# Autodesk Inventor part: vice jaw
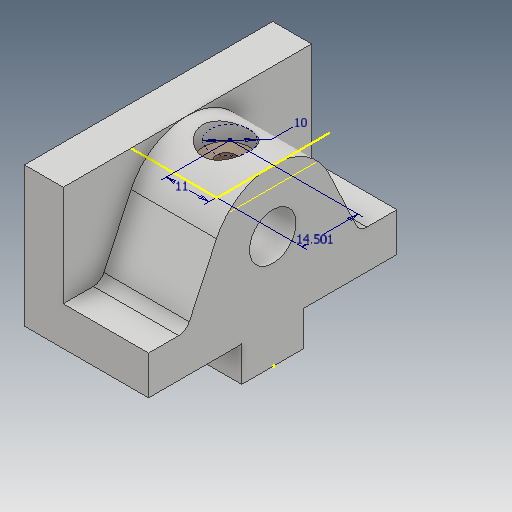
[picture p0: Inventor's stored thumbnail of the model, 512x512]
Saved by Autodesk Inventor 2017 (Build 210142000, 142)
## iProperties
Created: 2016-03
Part Number: vice jaw
Material: Generic
Document SubType Name: Modeling
Designer: Sandeep
Density: 1 g/cm^3
Appearance: Default
Author: Sandeep
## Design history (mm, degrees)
sketch "Sketch1"
  geometry: L1 (0, 0)-(-32, 0); L2 (-32, 0)-(-32, 36); L3 (-32, 36)-(-22, 36); L4 (-22, 36)-(-22, 10); L5 (-22, 10)-(0, 10); L6 (0, 10)-(0, 0)
  constraints: 12 end point, 5 perpendicular, 1 horizontal
  dimensions: "d0" = 36 distance between parallel lines of L1 L3; "d1" = 32 distance of L1.start L1.end; "d2" = 10 distance of L5.end L1.start; "d3" = 10 distance of L2.end L3.end
extrude "Extrusion1" new body sketch "Sketch1" stored distance "d4" = 64; taper "d5" = 0 deg
sketch "Sketch2"
  geometry: L1 (64, 10)-(64, 0) reference; L2 (64, 10)-(64, 0); L3 (64, 0)-(54.317, 0); L4 (64, 0)-(0, 0) reference; L5 (54.317, 0)-(46.501, -16.762); L6 (0, 0)-(0, 10); L7 (0, 10)-(64, 10); L8 (64, -26)-(0, -26) reference; L9 (0, 0)-(9.683, 0); L10 (32, 10)-(32, -39.451); L11 (9.683, 0)-(17.499, -16.762); A1 r 16 centre (32, -10) between (17.499, -16.762) and (46.501, -16.762); 1 further point
  constraints: 16 end point, 3 point on line, 2 collinear, 2 perpendicular, 2 point on circle, 2 symmetric about line, 2 tangent, 1 centre point, 1 coincident, 1 vertical
  dimensions: "d8" = 16 radius of A1; "d9" = 50 deg angle of L11 L5
extrude "Extrusion2" join sketch "Sketch2" stored distance "d10" = 32; taper "d11" = 0 deg
fillet "Fillet1" dims "d12" = 3
sketch "Sketch3"
  geometry: L1 (40, 0)-(40, 9); L2 (40, 9)-(24, 9); L3 (24, 9)-(24, 0); L4 (24, 0)-(40, 0); L5 (0, 0)-(64, 0) reference; L6 (32, 0)-(32, -54.171)
  constraints: 10 end point, 2 perpendicular, 2 vertical, 1 collinear, 1 point on line, 1 other
  dimensions: "d13" = 16 distance between parallel lines of L3 L1; "d14" = 9 distance of L2.end L3.end
extrude "Extrusion3" join sketch "Sketch3" stored distance "d15" = 32; taper "d16" = 0 deg
sketch "Sketch4"
  geometry: L1 (-24, 19)-(-40, 19) reference; L2 (-32, 19)-(-32, -29.453); C1 r 6 at (-32, -10); A1 r 16 centre (-32, -10) between (-46.501, -16.762) and (-17.499, -16.762) reference; 1 further point
  constraints: 2 end point, 1 centre point, 1 concentric, 1 midpoint, 1 point on line, 1 vertical
  dimensions: "d17" = 12 diameter of C1
extrude "Extrusion4" cut sketch "Sketch4" distance "d18" = 24; taper "d19" = 0 deg
sketch "Sketch6"
  geometry: 1 further point
workplane "Work Plane1"
sketch "Sketch7"
  geometry: L1 (14.501, 0)-(-14.501, 0) reference; L2 (14.501, 0)-(14.501, -22) reference; C1 r 5 at (0, -11); 1 further point
  constraints: 1 centre point
  dimensions: "d22" = 10 diameter of C1; "d23" = 11 distance from line of L1 C1.centre; "d24" = 14.50092 distance from line of C1.centre L2
workplane "Work Plane2"
hole "Hole1" diameter "d37" = 4.917; stored, may be unused: countersink angle "d41" = 90 deg, drill point angle "d43" = 118 deg; dims "d35" = 8, "d36" = 8, "d38" = 12, "d39" = 4, "d40" = 2, "d42" = 16
hole "Hole2" diameter "d46" = 4.917; stored, may be unused: countersink angle "d50" = 90 deg, drill point angle "d52" = 118 deg; dims "d44" = 8, "d45" = 8, "d47" = 12, "d48" = 4, "d49" = 2, "d51" = 16
hole "Hole3" diameter "d55" = 4.917; stored, may be unused: countersink angle "d59" = 82 deg, drill point angle "d61" = 118 deg; dims "d53" = 20, "d54" = 32, "d56" = 12, "d57" = 12, "d58" = 5, "d60" = 17.1
sketch "Sketch10"
  geometry: 1 further point
body "Solid1"
